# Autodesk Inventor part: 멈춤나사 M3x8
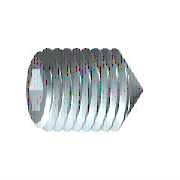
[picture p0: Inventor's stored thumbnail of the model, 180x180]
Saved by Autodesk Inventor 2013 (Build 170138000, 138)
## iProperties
IsCustomPart: 1
Created: 2012-02
Part Number: 멈춤나사 M3x8
Material: 강철, 연강
Description: 6각 소켓 머리 없는 멈춤 나사
Document SubType Name: Modeling
Standard: KS B 1028
Designer: test
Standards Organization: KS
Language: ko-KR
Size Designation: 원추점 M3x8
Categories: <MemberInstance><Categories><Category DisplayName="조임쇠" InternalName="e4da775c-781d-43d5-af7c-5136215cf5a6" Mnemonic="FSTN"><Category DisplayName="볼트" InternalN
Density: 1 g/cm^3
Author: test
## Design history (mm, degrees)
sketch "스케치1"
  geometry: L1 (0, 0)-(5.5, 0); L2 (8, 0.866)-(8, 1.5); L3 (8, 1.5)-(0, 1.5); L4 (8, 0.866)-(6, 0.866); L5 (6, 0.866)-(5.5, 0); L6 (0, -0.3)-(0, 1.8) reference; L7 (0, 1.5)-(0, 0)
  constraints: 13 end point, 3 parallel, 1 collinear, 1 perpendicular, 1 point on line
  dimensions: "d0" = 2 distance of L2.start L4.end (= INTI); "d1" = 60 deg angle of L5 L1; "d2" = 3 diameter of L3 L1 (= NND); "d3" = 1.73205 diameter of L4 L1 (= 1.1547 x SW); "d5" = 8 distance from line of L2 L3.end (= NLG)
revolve "본체" sketch "스케치1" stored, may be unused: angle "d6" = 90 deg
sketch "스케치2"
  geometry: L1 (-0.433, 0.75)-(0.433, 0.75); L2 (0.433, 0.75)-(0.866, 0); L3 (0.866, 0)-(0.433, -0.75); L4 (0.433, -0.75)-(-0.433, -0.75); L5 (-0.433, -0.75)-(-0.866, 0); L6 (-0.866, 0)-(-0.433, 0.75); 3 further points
  constraints: 12 end point, 1 coincident, 1 horizontal, 13 other
extrude "슬롯" join sketch "스케치2" taper "d7" = 0 deg; stored distance "d21" = 10
workaxis "Work Axis1"
workplane "Work Plane1"
sketch "스케치4"
  geometry: L1 (0, 0.15)-(-1.35, 1.5) reference; L2 (0, -0.15)-(-1.35, -1.5) reference; L3 (-1.35, -1.5)-(0.15, 0); L4 (-1.35, 1.5)-(0.15, 0); 2 further points
  constraints: 4 end point, 1 coincident, 1 collinear, 1 horizontal alignment
body "Solid1"
feature "스레드" dims "d12" = 8 (= NLG), "d13" = 0
chamfer "모따기1" distance "d8" = 1.35 (computed from NND, SPD, FAWI); stored, may be unused: angle "d9" = 45 deg (= FAWI), second distance "d34" = 1.35 (computed from NND, SPD, FAWI)
chamfer "모따기2" distance "d10" = 0.30673 (= -0.5 x GD1 + 0.5 x NND); stored, may be unused: angle "d11" = 45 deg (= FAWI), second distance "d35" = 0.30673 (= -0.5 x GD1 + 0.5 x NND)
other parameters: "NND" = 3 [user parameter; used in 5 equation terms], "NLG" = 8 [user parameter; used in 2 equation terms], "INTI" = 2 [user parameter; used in 1 equation term], "FAWI" = 45 deg [user parameter; used in 4 equation terms], "SW" = 1.5 [user parameter; used in 2 equation terms], "GD1" = 2.38655 (= THREADDIA - 1.2269 x PTC) [user parameter; used in 2 equation terms], "d4" = 0, "FAWI1" = 45 deg [user parameter], "SPD" = 0.3 [user parameter; used in 2 equation terms], "d36" = 0, "d37" = 0, "GUL" = 0.30673 (= 0.61345 x PTC) [user parameter], "TOA" = 30 deg [user parameter], "THREADDIA" = 3 [user parameter; used in 1 equation term], "PTC" = 0.5 [user parameter; used in 4 equation terms], "GAL" = 0.30673 (= 0.61345 x PTC) [user parameter], "E0" = 1.7325 (= 1.155 x SW) [user parameter]
